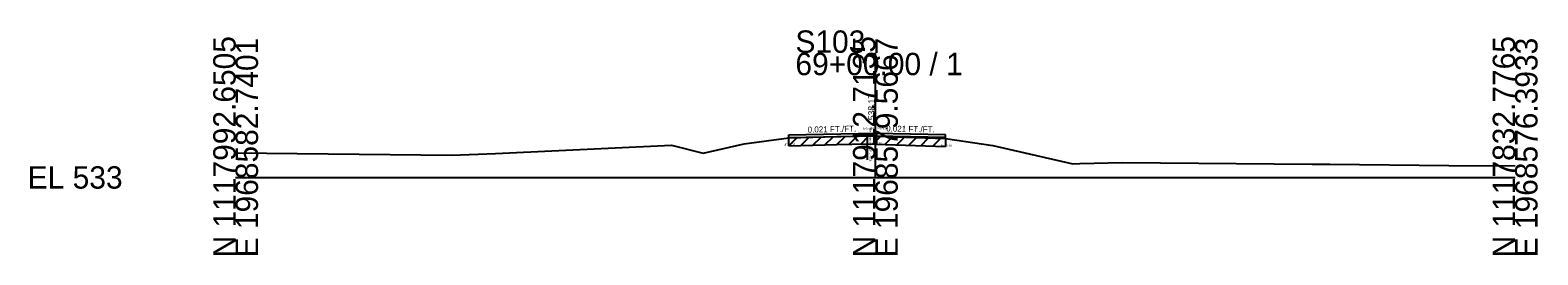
# Model space of a CAD drawing. Extents: x -26 to 163, y -10 to 24018.
# Drawn here: x -25.7 to 162.8, y 16990.3 to 17018.4 of the extents above; entities that cross this region are included whole.
import ezdxf

# ---------------------------------------------------------------- set-up
doc = ezdxf.new("R2010")
doc.units = 0
for name, color, linetype in [('RD_GPK_XS_Cell', 7, 'Continuous'), ('RD_XS_ExGround', 7, 'Continuous'), ('RD_XS_ExPaveRet', 7, 'Continuous'), ('RD_XS_Misc_Line', 7, 'Continuous'), ('RD_XS_PaveOvlay_CP', 7, 'Continuous'), ('RD_XS_TX_Elev_EX', 7, 'Continuous'), ('RD_XS_TX_ExEOP', 7, 'Continuous'), ('RD_XS_TX_Notes', 7, 'Continuous'), ('RD_XS_TX_Profile', 7, 'Continuous'), ('RD_XS_TX_Slope', 7, 'Continuous')]:
    doc.layers.add(name, color=color, linetype=linetype)

msp = doc.modelspace()

# ---------------------------------------------------------------- linework, layer by layer
at = {"layer": 'RD_GPK_XS_Cell'}
for p, q in [((80, 17000), (80, 17015.6)), ((0, 17000), (80, 17000)), ((80, 17000), (160, 17000))]:
    msp.add_line(p, q, dxfattribs=at)
at = {"layer": 'RD_XS_ExGround'}
msp.add_lwpolyline([(0, 17003.06), (27.05, 17002.78), (32.49, 17003), (54.5, 17004.04), (58.45, 17003.02), (63.58, 17004.2), (69.19, 17004.97), (75.2, 17005.11), (78.99, 17005.2), (80, 17005.17), (88.78, 17004.87), (94.7, 17004.01), (104.7, 17001.72), (105.58, 17001.74), (110.91, 17001.86), (134.62, 17001.67), (136.81, 17001.66), (151.72, 17001.51), (160, 17001.44)], dxfattribs=at)
at = {"layer": 'RD_XS_ExPaveRet'}
for p, q in [((69.19, 17003.97), (70.21, 17004.99)), ((69.19, 17003.97), (69.19, 17004.97)), ((69.19, 17003.97), (75.2, 17004.11)), ((70.69, 17004), (71.71, 17005.03)), ((72.19, 17004.04), (73.21, 17005.06)), ((73.69, 17004.07), (74.71, 17005.1)), ((75.19, 17004.11), (76.21, 17005.13)), ((75.2, 17004.11), (78.99, 17004.2)), ((76.69, 17004.14), (77.71, 17005.17)), ((78.19, 17004.18), (79.2, 17005.19)), ((78.99, 17004.2), (80, 17004.17)), ((79.69, 17004.18), (80.66, 17005.14)), ((80, 17004.17), (88.78, 17003.87)), ((81.19, 17004.12), (82.16, 17005.09)), ((82.69, 17004.07), (83.66, 17005.04)), ((84.19, 17004.02), (85.16, 17004.99)), ((85.69, 17003.97), (86.66, 17004.94)), ((87.19, 17003.92), (88.16, 17004.89)), ((88.78, 17004.87), (88.78, 17003.87))]:
    msp.add_line(p, q, dxfattribs=at)
at = {"layer": 'RD_XS_Misc_Line'}
msp.add_line((78.99, 17005.2), (78.99, 17002.2), dxfattribs=at)
at = {"layer": 'RD_XS_PaveOvlay_CP'}
for p, q in [((69.19, 17005.32), (80, 17005.54)), ((69.19, 17004.97), (69.19, 17005.32)), ((80, 17005.17), (69.19, 17004.94)), ((80, 17005.54), (88.78, 17005.36)), ((88.78, 17004.98), (80, 17005.17)), ((88.78, 17004.87), (88.78, 17005.36))]:
    msp.add_line(p, q, dxfattribs=at)

# ---------------------------------------------------------------- texts
at = {"layer": 'RD_GPK_XS_Cell'}
for s, p in [('N 1117992.6505', (0, 16990)), ('E 1968582.7401', (2.8, 16990)), ('N 1117912.7135', (80, 16990)), ('E 1968579.5667', (82.8, 16990)), ('N 1117832.7765', (160, 16990)), ('E 1968576.3933', (162.8, 16990))]:
    msp.add_text(s, height=2.8, rotation=90, dxfattribs=at).set_placement(p)
for s, p in [('S103', (70, 17015.6)), ('69+00.00 / 1', (70, 17012.8)), ('EL 533', (-26, 16998.6))]:
    msp.add_text(s, height=2.8, dxfattribs=at).set_placement(p)
at = {"layer": 'RD_XS_TX_Elev_EX'}
msp.add_text('538.17', height=0.8, rotation=90, dxfattribs=at).set_placement((79.9, 17007.17))
at = {"layer": 'RD_XS_TX_ExEOP'}
for s, p in [('EOP-L', (69.14, 17005.32)), ('EOP-R', (88.73, 17005.36))]:
    msp.add_text(s, height=0.1, rotation=270, dxfattribs=at).set_placement(p)
at = {"layer": 'RD_XS_TX_Notes'}
for s, p in [('Elev. @CL = 538.54', (78.47, 17006.04)), (' dE= 0.35', (68.48, 17003.97)), (' dE= 0.38', (79.29, 17004.17)), (' dE= 0.49', (88.07, 17003.87))]:
    msp.add_text(s, height=0.25, dxfattribs=at).set_placement(p)
msp.add_text(' Min. Distance @CP = -0.06', height=0.25, rotation=270, dxfattribs=at).set_placement((79.24, 17006.3))
at = {"layer": 'RD_XS_TX_Profile'}
msp.add_text('CL', height=0.25, dxfattribs=at).set_placement((79.77, 17005.54))
at = {"layer": 'RD_XS_TX_Slope'}
for rotation, p in [(1.1916, (71.54, 17005.61)), (358.8084, (81.34, 17005.76))]:
    msp.add_text('0.021 FT./FT.', height=0.75, rotation=rotation, dxfattribs=at).set_placement(p)

doc.saveas('drawing.dxf')
